// Mitsubishi GX Works2 project: 46.7台空压机轮休（位移指令）   PLC: FX3U/FX3UC

PROGRAM MAIN
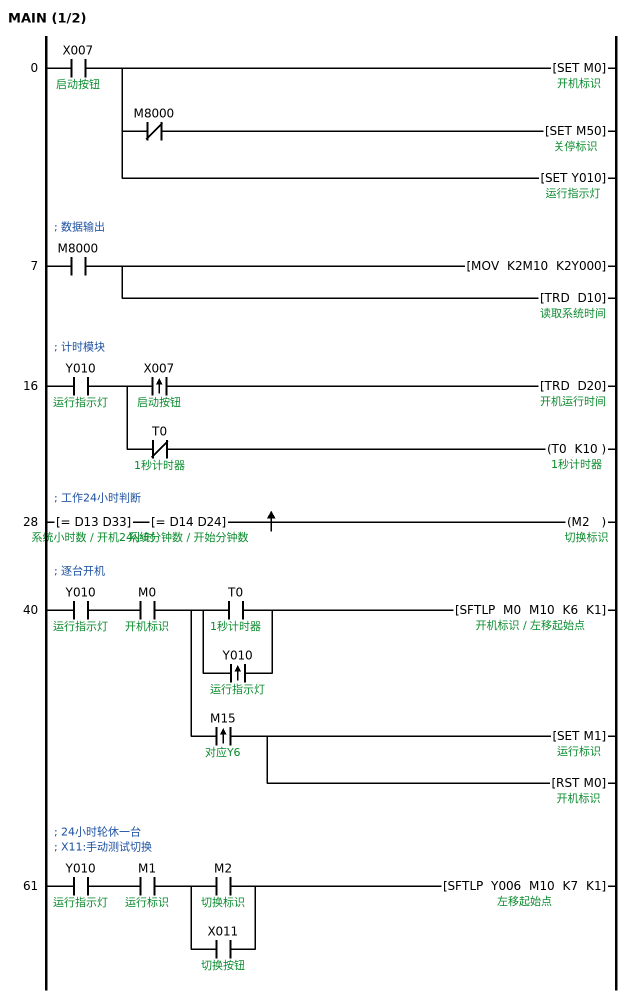
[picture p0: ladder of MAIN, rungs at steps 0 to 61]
0     LD      X007  ; 启动按钮
      SET     M0  ; 开机标识
      MPS
      ANI     M8000
      SET     M50  ; 关停标识
      MPP
      SET     Y010  ; 运行指示灯
; 数据输出
7     LD      M8000
      MOV     K2M10 K2Y000  ; 左移起始点 / 空压机
      TRD     D10  ; 读取系统时间
; 计时模块
16    LD      Y010  ; 运行指示灯
      MPS
      ANDP    X007  ; 启动按钮
      TRD     D20  ; 开机运行时间
      MPP
      ANI     T0  ; 1秒计时器
      OUT     T0 K10  ; 1秒计时器
; 工作24小时判断
28    LD=     D13 D33  ; 系统小时数 / 开机24小时
      AND=    D14 D24  ; 系统分钟数 / 开始分钟数
      MEP
      OUT     M2  ; 切换标识
; 逐台开机
40    LD      Y010  ; 运行指示灯
      AND     M0  ; 开机标识
      MPS
      LD      T0  ; 1秒计时器
      ORP     Y010  ; 运行指示灯
      ANB
      SFTLP   M0 M10 K6 K1
      MPP
      ANDP    M15  ; 对应Y6
      SET     M1  ; 运行标识
      RST     M0  ; 开机标识
; 24小时轮休一台
; X11:手动测试切换
61    LD      Y010  ; 运行指示灯
      AND     M1  ; 运行标识
      LD      M2  ; 切换标识
      OR      X011  ; 切换按钮
      ANB
      SFTLP   Y006 M10 K7 K1
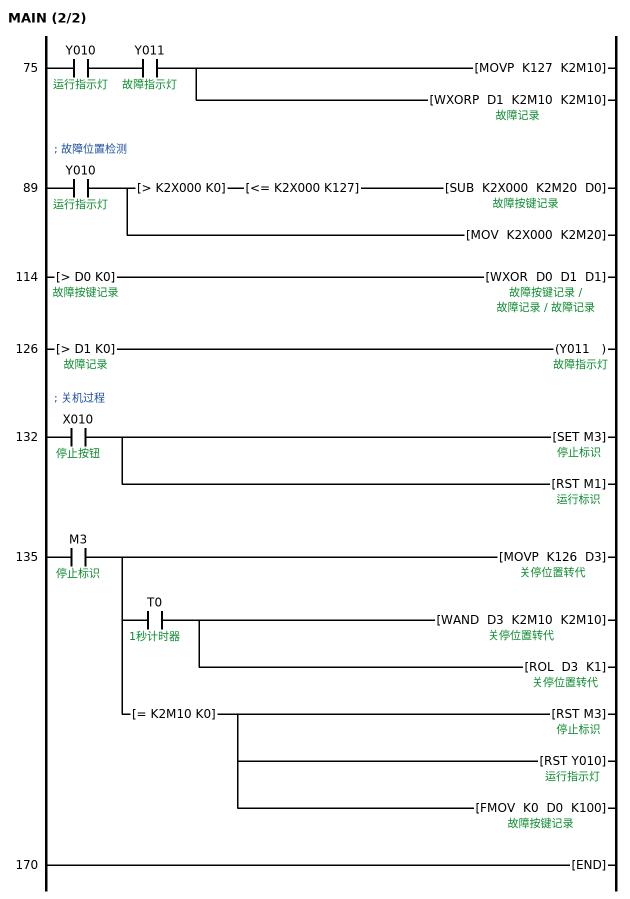
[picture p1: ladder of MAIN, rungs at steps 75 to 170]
75    LD      Y010  ; 运行指示灯
      AND     Y011  ; 故障指示灯
      MOVP    K127 K2M10
      WXORP   D1 K2M10 K2M10  ; 故障记录
; 故障位置检测
89    LD      Y010  ; 运行指示灯
      MPS
      AND>    K2X000 K0  ; 故障输入点
      AND<=   K2X000 K127  ; 故障输入点
      SUB     K2X000 K2M20 D0  ; 故障按键记录 / 故障按键记录
      MPP
      MOV     K2X000 K2M20
114   LD>     D0 K0  ; 故障按键记录
      WXOR    D0 D1 D1
126   LD>     D1 K0  ; 故障记录
      OUT     Y011  ; 故障指示灯
; 关机过程
132   LD      X010  ; 停止按钮
      SET     M3  ; 停止标识
      RST     M1  ; 运行标识
135   LD      M3  ; 停止标识
      MOVP    K126 D3  ; 关停位置转代
        [note] K126=Y0为0，其他为1
      MPS
      AND     T0  ; 1秒计时器
      WAND    D3 K2M10 K2M10
      ROL     D3 K1
      MPP
      AND=    K2M10 K0  ; 左移起始点
      RST     M3  ; 停止标识
      RST     Y010  ; 运行指示灯
      FMOV    K0 D0 K100
        [note] 所有D里面数据清零
170   END
END_PROGRAM

// device comments not shown above
T1  ; 关机计时
D2  ; 关停检测
D23  ; 开机小时数
D30  ; 读取系统时间
